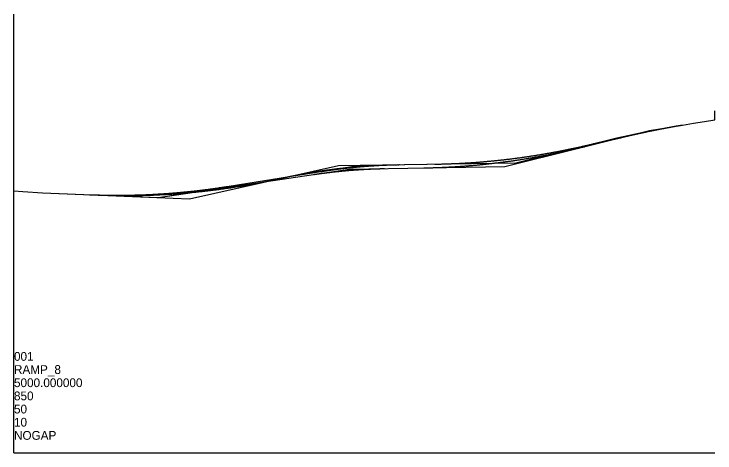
# Model space of a CAD drawing. Extents: x -26 to 16974102, y -10 to 12551234.
# Drawn here: x 179185 to 180784, y 178920 to 179920 of the extents above; entities that cross this region are included whole.
import ezdxf

# ---------------------------------------------------------------- set-up
doc = ezdxf.new("R2010")
doc.units = 0
for name, color, linetype in [('Level 28', 7, 'Continuous'), ('Level 30', 7, 'Continuous'), ('Level 31', 7, 'Continuous'), ('RD_GPK_Profile_Cell', 7, 'Continuous')]:
    doc.layers.add(name, color=color, linetype=linetype)

msp = doc.modelspace()

# ---------------------------------------------------------------- linework, layer by layer
at = {"layer": 'Level 28'}
msp.add_lwpolyline([(179185.3, 179517.1), (179205.3, 179515.6), (179250.3, 179512.6), (179515.3, 179502), (179975.3, 179575.4), (180330.3, 179580.7), (180560.3, 179637.5), (180585.3, 179643.4), (180610.3, 179648.8), (180635.3, 179653.6), (180660.3, 179658.3), (180685.3, 179662.8), (180710.3, 179667), (180735.3, 179671), (180760.3, 179674.9), (180784.4, 179678.5), (180784.4, 179682), (180784.4, 179685.3), (180784.4, 179688.6), (180784.4, 179692.1), (180784.4, 179695.5), (180784.4, 179698.8), (180784.4, 179699.2)], dxfattribs=at)
for points in [[(180145.3, 179577.9), (180149, 179578), (180152.7, 179578.1), (180156.4, 179578.2), (180160.1, 179578.2), (180163.8, 179578.3), (180167.5, 179578.4), (180171.2, 179578.5), (180174.9, 179578.7), (180178.6, 179578.8), (180182.3, 179578.9), (180186, 179579.1), (180189.7, 179579.2), (180193.4, 179579.4), (180197.1, 179579.6), (180200.8, 179579.7), (180204.5, 179579.9), (180208.2, 179580.1), (180211.9, 179580.3), (180215.6, 179580.5), (180219.3, 179580.8), (180223, 179581), (180226.7, 179581.2), (180230.4, 179581.5), (180234.1, 179581.7), (180237.8, 179582), (180241.5, 179582.3), (180245.2, 179582.6), (180248.9, 179582.9), (180252.6, 179583.2), (180256.3, 179583.5), (180260, 179583.8), (180263.7, 179584.1), (180267.4, 179584.5), (180271.1, 179584.8), (180274.8, 179585.1), (180278.5, 179585.5), (180282.2, 179585.9), (180285.9, 179586.3), (180289.6, 179586.6), (180293.3, 179587), (180297, 179587.4), (180300.7, 179587.8), (180304.4, 179588.3), (180308.1, 179588.7), (180311.8, 179589.1), (180315.5, 179589.6), (180319.2, 179590), (180322.9, 179590.5), (180326.6, 179591), (180330.3, 179591.4), (180334, 179591.9), (180337.7, 179592.4), (180341.4, 179592.9), (180345.1, 179593.5), (180348.8, 179594), (180352.5, 179594.5), (180356.2, 179595.1), (180359.9, 179595.6), (180363.6, 179596.2), (180367.3, 179596.7), (180371, 179597.3), (180374.7, 179597.9), (180378.4, 179598.5), (180382.1, 179599.1), (180385.8, 179599.7), (180389.5, 179600.3), (180393.2, 179600.9), (180396.9, 179601.6), (180400.6, 179602.2), (180404.3, 179602.9), (180408, 179603.5), (180411.7, 179604.2), (180415.4, 179604.9), (180419.1, 179605.6), (180422.8, 179606.2), (180426.5, 179607), (180430.2, 179607.7), (180433.9, 179608.4), (180437.6, 179609.1), (180441.3, 179609.9), (180445, 179610.6), (180448.7, 179611.4), (180452.4, 179612.1), (180456.1, 179612.9), (180459.8, 179613.7), (180463.5, 179614.5), (180467.2, 179615.3), (180470.9, 179616.1), (180474.6, 179616.9), (180478.3, 179617.7), (180482, 179618.5), (180485.7, 179619.4), (180489.4, 179620.2), (180493.1, 179621.1), (180496.8, 179621.9), (180500.5, 179622.8), (180504.2, 179623.7), (180507.9, 179624.6), (180511.6, 179625.5), (180515.3, 179626.4)], [(179885.3, 179561), (179887.1, 179561.3), (179888.9, 179561.6), (179890.7, 179561.9), (179892.5, 179562.2), (179894.3, 179562.4), (179896.1, 179562.7), (179897.9, 179563), (179899.7, 179563.3), (179901.5, 179563.5), (179903.3, 179563.8), (179905.1, 179564), (179906.9, 179564.3), (179908.7, 179564.6), (179910.5, 179564.8), (179912.3, 179565.1), (179914.1, 179565.3), (179915.9, 179565.5), (179917.7, 179565.8), (179919.5, 179566), (179921.3, 179566.3), (179923.1, 179566.5), (179924.9, 179566.7), (179926.7, 179567), (179928.5, 179567.2), (179930.3, 179567.4), (179932.1, 179567.6), (179933.9, 179567.8), (179935.7, 179568.1), (179937.5, 179568.3), (179939.3, 179568.5), (179941.1, 179568.7), (179942.9, 179568.9), (179944.7, 179569.1), (179946.5, 179569.3), (179948.3, 179569.5), (179950.1, 179569.7), (179951.9, 179569.9), (179953.7, 179570.1), (179955.5, 179570.3), (179957.3, 179570.4), (179959.1, 179570.6), (179960.9, 179570.8), (179962.7, 179571), (179964.5, 179571.2), (179966.3, 179571.3), (179968.1, 179571.5), (179969.9, 179571.7), (179971.7, 179571.8), (179973.5, 179572), (179975.3, 179572.1), (179977.1, 179572.3), (179978.9, 179572.5), (179980.7, 179572.6), (179982.5, 179572.8), (179984.3, 179572.9), (179986.1, 179573), (179987.9, 179573.2), (179989.7, 179573.3), (179991.5, 179573.5), (179993.3, 179573.6), (179995.1, 179573.7), (179996.9, 179573.8), (179998.7, 179574), (180000.5, 179574.1), (180002.3, 179574.2), (180004.1, 179574.3), (180005.9, 179574.4), (180007.7, 179574.5), (180009.5, 179574.7), (180011.3, 179574.8), (180013.1, 179574.9), (180014.9, 179575), (180016.7, 179575.1), (180018.5, 179575.2), (180020.3, 179575.3), (180022.1, 179575.3), (180023.9, 179575.4), (180025.7, 179575.5), (180027.5, 179575.6), (180029.3, 179575.7), (180031.1, 179575.8), (180032.9, 179575.8), (180034.7, 179575.9), (180036.5, 179576), (180038.3, 179576), (180040.1, 179576.1), (180041.9, 179576.2), (180043.7, 179576.2), (180045.5, 179576.3), (180047.3, 179576.3), (180049.1, 179576.4), (180050.9, 179576.4), (180052.7, 179576.5), (180054.5, 179576.5), (180056.3, 179576.6), (180058.1, 179576.6), (180059.9, 179576.7), (180061.7, 179576.7), (180063.5, 179576.7), (180065.3, 179576.7)], [(179357.7, 179508.3), (179360.9, 179508.2), (179364, 179508.1), (179367.2, 179508), (179370.3, 179507.9), (179373.5, 179507.8), (179376.6, 179507.7), (179379.8, 179507.6), (179382.9, 179507.5), (179386.1, 179507.4), (179389.2, 179507.4), (179392.4, 179507.3), (179395.5, 179507.3), (179398.7, 179507.2), (179401.8, 179507.2), (179405, 179507.1), (179408.2, 179507.1), (179411.3, 179507.1), (179414.5, 179507.1), (179417.6, 179507.1), (179420.8, 179507), (179423.9, 179507.1), (179427.1, 179507.1), (179430.2, 179507.1), (179433.4, 179507.1), (179436.5, 179507.1), (179439.7, 179507.2), (179442.8, 179507.2), (179446, 179507.2), (179449.1, 179507.3), (179452.3, 179507.4), (179455.4, 179507.4), (179458.6, 179507.5), (179461.8, 179507.6), (179464.9, 179507.7), (179468.1, 179507.8), (179471.2, 179507.8), (179474.4, 179508), (179477.5, 179508.1), (179480.7, 179508.2), (179483.8, 179508.3), (179487, 179508.4), (179490.1, 179508.6), (179493.3, 179508.7), (179496.4, 179508.9), (179499.6, 179509), (179502.7, 179509.2), (179505.9, 179509.3), (179509, 179509.5), (179512.2, 179509.7), (179515.3, 179509.9), (179518.5, 179510.1), (179521.7, 179510.3), (179524.8, 179510.5), (179528, 179510.7), (179531.1, 179510.9), (179534.3, 179511.1), (179537.4, 179511.3), (179540.6, 179511.6), (179543.7, 179511.8), (179546.9, 179512.1), (179550, 179512.3), (179553.2, 179512.6), (179556.3, 179512.9), (179559.5, 179513.1), (179562.6, 179513.4), (179565.8, 179513.7), (179568.9, 179514), (179572.1, 179514.3), (179575.3, 179514.6), (179578.4, 179514.9), (179581.6, 179515.2), (179584.7, 179515.5), (179587.9, 179515.9), (179591, 179516.2), (179594.2, 179516.5), (179597.3, 179516.9), (179600.5, 179517.3), (179603.6, 179517.6), (179606.8, 179518), (179609.9, 179518.4), (179613.1, 179518.7), (179616.2, 179519.1), (179619.4, 179519.5), (179622.5, 179519.9), (179625.7, 179520.3), (179628.8, 179520.7), (179632, 179521.1), (179635.2, 179521.6), (179638.3, 179522), (179641.5, 179522.4), (179644.6, 179522.9), (179647.8, 179523.3), (179650.9, 179523.8), (179654.1, 179524.3), (179657.2, 179524.7), (179660.4, 179525.2), (179663.5, 179525.7), (179666.7, 179526.2), (179669.8, 179526.7), (179673, 179527.2)]]:
    msp.add_spline(points, degree=3, dxfattribs=at)
at = {"layer": 'Level 30'}
msp.add_lwpolyline([(179185.3, 179517.1), (179205.3, 179515.6), (179250.3, 179512.6), (179515.3, 179502), (179950.3, 179566.4), (180305.3, 179572.6), (180635.3, 179654.7), (180710.3, 179667), (180735.3, 179671), (180760.3, 179674.9), (180784.4, 179678.5), (180784.4, 179682), (180784.4, 179685.3), (180784.4, 179688.6), (180784.4, 179692.1), (180784.4, 179695.5), (180784.4, 179698.8), (180784.4, 179699.2)], dxfattribs=at)
for points in [[(180560.3, 179636), (180561.8, 179636.4), (180563.3, 179636.7), (180564.8, 179637.1), (180566.3, 179637.5), (180567.8, 179637.9), (180569.3, 179638.2), (180570.8, 179638.6), (180572.3, 179638.9), (180573.8, 179639.3), (180575.3, 179639.7), (180576.8, 179640), (180578.3, 179640.4), (180579.8, 179640.7), (180581.3, 179641.1), (180582.8, 179641.5), (180584.3, 179641.8), (180585.8, 179642.2), (180587.3, 179642.5), (180588.8, 179642.9), (180590.3, 179643.2), (180591.8, 179643.6), (180593.3, 179643.9), (180594.8, 179644.2), (180596.3, 179644.6), (180597.8, 179644.9), (180599.3, 179645.3), (180600.8, 179645.6), (180602.3, 179646), (180603.8, 179646.3), (180605.3, 179646.6), (180606.8, 179647), (180608.3, 179647.3), (180609.8, 179647.6), (180611.3, 179648), (180612.8, 179648.3), (180614.3, 179648.6), (180615.8, 179648.9), (180617.3, 179649.3), (180618.8, 179649.6), (180620.3, 179649.9), (180621.8, 179650.2), (180623.3, 179650.6), (180624.8, 179650.9), (180626.3, 179651.2), (180627.8, 179651.5), (180629.3, 179651.8), (180630.8, 179652.1), (180632.3, 179652.5), (180633.8, 179652.8), (180635.3, 179653.1), (180636.8, 179653.4), (180638.3, 179653.7), (180639.8, 179654), (180641.3, 179654.3), (180642.8, 179654.6), (180644.3, 179654.9), (180645.8, 179655.2), (180647.3, 179655.5), (180648.8, 179655.8), (180650.3, 179656.1), (180651.8, 179656.4), (180653.3, 179656.7), (180654.8, 179657), (180656.3, 179657.3), (180657.8, 179657.6), (180659.3, 179657.9), (180660.8, 179658.2), (180662.3, 179658.5), (180663.8, 179658.8), (180665.3, 179659), (180666.8, 179659.3), (180668.3, 179659.6), (180669.8, 179659.9), (180671.3, 179660.2), (180672.8, 179660.5), (180674.3, 179660.7), (180675.8, 179661), (180677.3, 179661.3), (180678.8, 179661.6), (180680.3, 179661.8), (180681.8, 179662.1), (180683.3, 179662.4), (180684.8, 179662.6), (180686.3, 179662.9), (180687.8, 179663.2), (180689.3, 179663.4), (180690.8, 179663.7), (180692.3, 179664), (180693.8, 179664.2), (180695.3, 179664.5), (180696.8, 179664.8), (180698.3, 179665), (180699.8, 179665.3), (180701.3, 179665.5), (180702.8, 179665.8), (180704.3, 179666), (180705.8, 179666.3), (180707.3, 179666.5), (180708.8, 179666.8), (180710.3, 179667)], [(180120.3, 179569.3), (180124, 179569.4), (180127.7, 179569.5), (180131.4, 179569.6), (180135.1, 179569.7), (180138.8, 179569.8), (180142.5, 179569.9), (180146.2, 179570), (180149.9, 179570.1), (180153.6, 179570.3), (180157.3, 179570.4), (180161, 179570.6), (180164.7, 179570.7), (180168.4, 179570.9), (180172.1, 179571.1), (180175.8, 179571.3), (180179.5, 179571.5), (180183.2, 179571.7), (180186.9, 179571.9), (180190.6, 179572.1), (180194.3, 179572.3), (180198, 179572.6), (180201.7, 179572.8), (180205.4, 179573.1), (180209.1, 179573.4), (180212.8, 179573.6), (180216.5, 179573.9), (180220.2, 179574.2), (180223.9, 179574.5), (180227.6, 179574.8), (180231.3, 179575.1), (180235, 179575.5), (180238.7, 179575.8), (180242.4, 179576.1), (180246.1, 179576.5), (180249.8, 179576.8), (180253.5, 179577.2), (180257.2, 179577.6), (180260.9, 179578), (180264.6, 179578.4), (180268.3, 179578.8), (180272, 179579.2), (180275.7, 179579.6), (180279.4, 179580), (180283.1, 179580.5), (180286.8, 179580.9), (180290.5, 179581.4), (180294.2, 179581.8), (180297.9, 179582.3), (180301.6, 179582.8), (180305.3, 179583.3), (180309, 179583.8), (180312.7, 179584.3), (180316.4, 179584.8), (180320.1, 179585.3), (180323.8, 179585.8), (180327.5, 179586.4), (180331.2, 179586.9), (180334.9, 179587.5), (180338.6, 179588), (180342.3, 179588.6), (180346, 179589.2), (180349.7, 179589.8), (180353.4, 179590.4), (180357.1, 179591), (180360.8, 179591.6), (180364.5, 179592.2), (180368.2, 179592.9), (180371.9, 179593.5), (180375.6, 179594.2), (180379.3, 179594.8), (180383, 179595.5), (180386.7, 179596.2), (180390.4, 179596.9), (180394.1, 179597.6), (180397.8, 179598.3), (180401.5, 179599), (180405.2, 179599.7), (180408.9, 179600.4), (180412.6, 179601.1), (180416.3, 179601.9), (180420, 179602.6), (180423.7, 179603.4), (180427.4, 179604.2), (180431.1, 179605), (180434.8, 179605.7), (180438.5, 179606.5), (180442.2, 179607.3), (180445.9, 179608.2), (180449.6, 179609), (180453.3, 179609.8), (180457, 179610.7), (180460.7, 179611.5), (180464.4, 179612.4), (180468.1, 179613.2), (180471.8, 179614.1), (180475.5, 179615), (180479.2, 179615.9), (180482.9, 179616.8), (180486.6, 179617.7), (180490.3, 179618.6)], [(179870.3, 179554.5), (179871.9, 179554.8), (179873.5, 179555), (179875.1, 179555.2), (179876.7, 179555.5), (179878.3, 179555.7), (179879.9, 179555.9), (179881.5, 179556.1), (179883.1, 179556.4), (179884.7, 179556.6), (179886.3, 179556.8), (179887.9, 179557), (179889.5, 179557.2), (179891.1, 179557.4), (179892.7, 179557.6), (179894.3, 179557.8), (179895.9, 179558), (179897.5, 179558.2), (179899.1, 179558.4), (179900.7, 179558.6), (179902.3, 179558.8), (179903.9, 179559), (179905.5, 179559.2), (179907.1, 179559.4), (179908.7, 179559.6), (179910.3, 179559.8), (179911.9, 179560), (179913.5, 179560.2), (179915.1, 179560.3), (179916.7, 179560.5), (179918.3, 179560.7), (179919.9, 179560.9), (179921.5, 179561), (179923.1, 179561.2), (179924.7, 179561.4), (179926.3, 179561.5), (179927.9, 179561.7), (179929.5, 179561.9), (179931.1, 179562), (179932.7, 179562.2), (179934.3, 179562.3), (179935.9, 179562.5), (179937.5, 179562.6), (179939.1, 179562.8), (179940.7, 179562.9), (179942.3, 179563.1), (179943.9, 179563.2), (179945.5, 179563.3), (179947.1, 179563.5), (179948.7, 179563.6), (179950.3, 179563.8), (179951.9, 179563.9), (179953.5, 179564), (179955.1, 179564.1), (179956.7, 179564.3), (179958.3, 179564.4), (179959.9, 179564.5), (179961.5, 179564.6), (179963.1, 179564.7), (179964.7, 179564.9), (179966.3, 179565), (179967.9, 179565.1), (179969.5, 179565.2), (179971.1, 179565.3), (179972.7, 179565.4), (179974.3, 179565.5), (179975.9, 179565.6), (179977.5, 179565.7), (179979.1, 179565.8), (179980.7, 179565.9), (179982.3, 179566), (179983.9, 179566.1), (179985.5, 179566.2), (179987.1, 179566.2), (179988.7, 179566.3), (179990.3, 179566.4), (179991.9, 179566.5), (179993.5, 179566.6), (179995.1, 179566.6), (179996.7, 179566.7), (179998.3, 179566.8), (179999.9, 179566.9), (180001.5, 179566.9), (180003.1, 179567), (180004.7, 179567), (180006.3, 179567.1), (180007.9, 179567.2), (180009.5, 179567.2), (180011.1, 179567.3), (180012.7, 179567.3), (180014.3, 179567.4), (180015.9, 179567.4), (180017.5, 179567.5), (180019.1, 179567.5), (180020.7, 179567.6), (180022.3, 179567.6), (180023.9, 179567.6), (180025.5, 179567.7), (180027.1, 179567.7), (180028.7, 179567.7), (180030.3, 179567.8)], [(179365.3, 179508), (179368.3, 179507.9), (179371.3, 179507.8), (179374.3, 179507.7), (179377.3, 179507.6), (179380.3, 179507.5), (179383.3, 179507.4), (179386.3, 179507.3), (179389.3, 179507.2), (179392.3, 179507.2), (179395.3, 179507.1), (179398.3, 179507), (179401.3, 179507), (179404.3, 179506.9), (179407.3, 179506.9), (179410.3, 179506.8), (179413.3, 179506.8), (179416.3, 179506.8), (179419.3, 179506.8), (179422.3, 179506.7), (179425.3, 179506.7), (179428.3, 179506.7), (179431.3, 179506.7), (179434.3, 179506.7), (179437.3, 179506.7), (179440.3, 179506.8), (179443.3, 179506.8), (179446.3, 179506.8), (179449.3, 179506.9), (179452.3, 179506.9), (179455.3, 179506.9), (179458.3, 179507), (179461.3, 179507.1), (179464.3, 179507.1), (179467.3, 179507.2), (179470.3, 179507.3), (179473.3, 179507.3), (179476.3, 179507.4), (179479.3, 179507.5), (179482.3, 179507.6), (179485.3, 179507.7), (179488.3, 179507.8), (179491.3, 179507.9), (179494.3, 179508.1), (179497.3, 179508.2), (179500.3, 179508.3), (179503.3, 179508.5), (179506.3, 179508.6), (179509.3, 179508.7), (179512.3, 179508.9), (179515.3, 179509.1), (179518.3, 179509.2), (179521.3, 179509.4), (179524.3, 179509.6), (179527.3, 179509.7), (179530.3, 179509.9), (179533.3, 179510.1), (179536.3, 179510.3), (179539.3, 179510.5), (179542.3, 179510.7), (179545.3, 179511), (179548.3, 179511.2), (179551.3, 179511.4), (179554.3, 179511.6), (179557.3, 179511.9), (179560.3, 179512.1), (179563.3, 179512.4), (179566.3, 179512.6), (179569.3, 179512.9), (179572.3, 179513.1), (179575.3, 179513.4), (179578.3, 179513.7), (179581.3, 179514), (179584.3, 179514.3), (179587.3, 179514.6), (179590.3, 179514.9), (179593.3, 179515.2), (179596.3, 179515.5), (179599.3, 179515.8), (179602.3, 179516.1), (179605.3, 179516.4), (179608.3, 179516.8), (179611.3, 179517.1), (179614.3, 179517.5), (179617.3, 179517.8), (179620.3, 179518.2), (179623.3, 179518.5), (179626.3, 179518.9), (179629.3, 179519.3), (179632.3, 179519.7), (179635.3, 179520), (179638.3, 179520.4), (179641.3, 179520.8), (179644.3, 179521.2), (179647.3, 179521.6), (179650.3, 179522), (179653.3, 179522.5), (179656.3, 179522.9), (179659.3, 179523.3), (179662.3, 179523.8), (179665.3, 179524.2)]]:
    msp.add_spline(points, degree=3, dxfattribs=at)
at = {"layer": 'Level 31'}
msp.add_lwpolyline([(179185.3, 179517.1), (179205.3, 179515.6), (179250.3, 179512.6), (179585.3, 179499.2), (179925.3, 179574.6), (180330.3, 179580.7), (180560.3, 179637.5), (180585.3, 179643.4), (180610.3, 179648.8), (180635.3, 179653.6), (180660.3, 179658.3), (180685.3, 179662.8), (180710.3, 179667), (180735.3, 179671), (180760.3, 179674.9), (180784.4, 179678.5), (180784.4, 179682), (180784.4, 179685.3), (180784.4, 179688.6), (180784.4, 179692.1), (180784.4, 179695.5), (180784.4, 179698.8), (180784.4, 179699.2)], dxfattribs=at)
for points in [[(180145.3, 179577.9), (180149, 179578), (180152.7, 179578.1), (180156.4, 179578.2), (180160.1, 179578.2), (180163.8, 179578.3), (180167.5, 179578.4), (180171.2, 179578.5), (180174.9, 179578.7), (180178.6, 179578.8), (180182.3, 179578.9), (180186, 179579.1), (180189.7, 179579.2), (180193.4, 179579.4), (180197.1, 179579.6), (180200.8, 179579.7), (180204.5, 179579.9), (180208.2, 179580.1), (180211.9, 179580.3), (180215.6, 179580.5), (180219.3, 179580.8), (180223, 179581), (180226.7, 179581.2), (180230.4, 179581.5), (180234.1, 179581.7), (180237.8, 179582), (180241.5, 179582.3), (180245.2, 179582.6), (180248.9, 179582.9), (180252.6, 179583.2), (180256.3, 179583.5), (180260, 179583.8), (180263.7, 179584.1), (180267.4, 179584.5), (180271.1, 179584.8), (180274.8, 179585.1), (180278.5, 179585.5), (180282.2, 179585.9), (180285.9, 179586.3), (180289.6, 179586.6), (180293.3, 179587), (180297, 179587.4), (180300.7, 179587.8), (180304.4, 179588.3), (180308.1, 179588.7), (180311.8, 179589.1), (180315.5, 179589.6), (180319.2, 179590), (180322.9, 179590.5), (180326.6, 179591), (180330.3, 179591.4), (180334, 179591.9), (180337.7, 179592.4), (180341.4, 179592.9), (180345.1, 179593.5), (180348.8, 179594), (180352.5, 179594.5), (180356.2, 179595.1), (180359.9, 179595.6), (180363.6, 179596.2), (180367.3, 179596.7), (180371, 179597.3), (180374.7, 179597.9), (180378.4, 179598.5), (180382.1, 179599.1), (180385.8, 179599.7), (180389.5, 179600.3), (180393.2, 179600.9), (180396.9, 179601.6), (180400.6, 179602.2), (180404.3, 179602.9), (180408, 179603.5), (180411.7, 179604.2), (180415.4, 179604.9), (180419.1, 179605.6), (180422.8, 179606.2), (180426.5, 179607), (180430.2, 179607.7), (180433.9, 179608.4), (180437.6, 179609.1), (180441.3, 179609.9), (180445, 179610.6), (180448.7, 179611.4), (180452.4, 179612.1), (180456.1, 179612.9), (180459.8, 179613.7), (180463.5, 179614.5), (180467.2, 179615.3), (180470.9, 179616.1), (180474.6, 179616.9), (180478.3, 179617.7), (180482, 179618.5), (180485.7, 179619.4), (180489.4, 179620.2), (180493.1, 179621.1), (180496.8, 179621.9), (180500.5, 179622.8), (180504.2, 179623.7), (180507.9, 179624.6), (180511.6, 179625.5), (180515.3, 179626.4)], [(179795.3, 179545.8), (179797.9, 179546.4), (179800.5, 179546.9), (179803.1, 179547.5), (179805.7, 179548.1), (179808.3, 179548.6), (179810.9, 179549.2), (179813.5, 179549.7), (179816.1, 179550.2), (179818.7, 179550.8), (179821.3, 179551.3), (179823.9, 179551.8), (179826.5, 179552.3), (179829.1, 179552.8), (179831.7, 179553.4), (179834.3, 179553.8), (179836.9, 179554.3), (179839.5, 179554.8), (179842.1, 179555.3), (179844.7, 179555.8), (179847.3, 179556.3), (179849.9, 179556.7), (179852.5, 179557.2), (179855.1, 179557.6), (179857.7, 179558.1), (179860.3, 179558.5), (179862.9, 179559), (179865.5, 179559.4), (179868.1, 179559.8), (179870.7, 179560.3), (179873.3, 179560.7), (179875.9, 179561.1), (179878.5, 179561.5), (179881.1, 179561.9), (179883.7, 179562.3), (179886.3, 179562.7), (179888.9, 179563.1), (179891.5, 179563.5), (179894.1, 179563.8), (179896.7, 179564.2), (179899.3, 179564.6), (179901.9, 179564.9), (179904.5, 179565.3), (179907.1, 179565.6), (179909.7, 179566), (179912.3, 179566.3), (179914.9, 179566.6), (179917.5, 179567), (179920.1, 179567.3), (179922.7, 179567.6), (179925.3, 179567.9), (179927.9, 179568.2), (179930.5, 179568.5), (179933.1, 179568.8), (179935.7, 179569.1), (179938.3, 179569.4), (179940.9, 179569.7), (179943.5, 179569.9), (179946.1, 179570.2), (179948.7, 179570.5), (179951.3, 179570.7), (179953.9, 179571), (179956.5, 179571.2), (179959.1, 179571.5), (179961.7, 179571.7), (179964.3, 179571.9), (179966.9, 179572.2), (179969.5, 179572.4), (179972.1, 179572.6), (179974.7, 179572.8), (179977.3, 179573), (179979.9, 179573.2), (179982.5, 179573.4), (179985.1, 179573.6), (179987.7, 179573.8), (179990.3, 179573.9), (179992.9, 179574.1), (179995.5, 179574.3), (179998.1, 179574.4), (180000.7, 179574.6), (180003.3, 179574.7), (180005.9, 179574.9), (180008.5, 179575), (180011.1, 179575.2), (180013.7, 179575.3), (180016.3, 179575.4), (180018.9, 179575.5), (180021.5, 179575.6), (180024.1, 179575.7), (180026.7, 179575.8), (180029.3, 179575.9), (180031.9, 179576), (180034.5, 179576.1), (180037.1, 179576.2), (180039.7, 179576.3), (180042.3, 179576.3), (180044.9, 179576.4), (180047.5, 179576.5), (180050.1, 179576.5), (180052.7, 179576.6), (180055.3, 179576.6)], [(179375.3, 179507.6), (179379.5, 179507.4), (179383.7, 179507.3), (179387.9, 179507.2), (179392.1, 179507), (179396.3, 179506.9), (179400.5, 179506.8), (179404.7, 179506.7), (179408.9, 179506.6), (179413.1, 179506.5), (179417.3, 179506.5), (179421.5, 179506.4), (179425.7, 179506.4), (179429.9, 179506.4), (179434.1, 179506.3), (179438.3, 179506.3), (179442.5, 179506.3), (179446.7, 179506.3), (179450.9, 179506.4), (179455.1, 179506.4), (179459.3, 179506.4), (179463.5, 179506.5), (179467.7, 179506.6), (179471.9, 179506.7), (179476.1, 179506.7), (179480.3, 179506.8), (179484.5, 179507), (179488.7, 179507.1), (179492.9, 179507.2), (179497.1, 179507.4), (179501.3, 179507.5), (179505.5, 179507.7), (179509.7, 179507.9), (179513.9, 179508.1), (179518.1, 179508.3), (179522.3, 179508.5), (179526.5, 179508.7), (179530.7, 179508.9), (179534.9, 179509.2), (179539.1, 179509.4), (179543.3, 179509.7), (179547.5, 179510), (179551.7, 179510.3), (179555.9, 179510.6), (179560.1, 179510.9), (179564.3, 179511.2), (179568.5, 179511.5), (179572.7, 179511.9), (179576.9, 179512.2), (179581.1, 179512.6), (179585.3, 179513), (179589.5, 179513.3), (179593.7, 179513.7), (179597.9, 179514.1), (179602.1, 179514.6), (179606.3, 179515), (179610.5, 179515.4), (179614.7, 179515.9), (179618.9, 179516.4), (179623.1, 179516.8), (179627.3, 179517.3), (179631.5, 179517.8), (179635.7, 179518.3), (179639.9, 179518.8), (179644.1, 179519.4), (179648.3, 179519.9), (179652.5, 179520.5), (179656.7, 179521), (179660.9, 179521.6), (179665.1, 179522.2), (179669.3, 179522.8), (179673.5, 179523.4), (179677.7, 179524), (179681.9, 179524.6), (179686.1, 179525.3), (179690.3, 179525.9), (179694.5, 179526.6), (179698.7, 179527.3), (179702.9, 179528), (179707.1, 179528.7), (179711.3, 179529.4), (179715.5, 179530.1), (179719.7, 179530.8), (179723.9, 179531.5), (179728.1, 179532.3), (179732.3, 179533.1), (179736.5, 179533.8), (179740.7, 179534.6), (179744.9, 179535.4), (179749.1, 179536.2), (179753.3, 179537), (179757.5, 179537.9), (179761.7, 179538.7), (179765.9, 179539.5), (179770.1, 179540.4), (179774.3, 179541.3), (179778.5, 179542.2), (179782.7, 179543.1), (179786.9, 179544), (179791.1, 179544.9), (179795.3, 179545.8)]]:
    msp.add_spline(points, degree=3, dxfattribs=at)
at = {"layer": 'RD_GPK_Profile_Cell'}
for q in [(179185.3, 179919.9), (180784.4, 178919.9), (179185.3, 178919.9)]:
    msp.add_line((179185.3, 178919.9), q, dxfattribs=at)

# ---------------------------------------------------------------- texts
for s, p in [('001', (179185.3, 179129.9)), ('RAMP_8', (179185.3, 179099.9)), ('5000.000000', (179185.3, 179069.9)), ('850', (179185.3, 179039.9)), ('50', (179185.3, 179009.9)), ('10', (179185.3, 178979.9)), ('NOGAP', (179185.3, 178949.9))]:
    msp.add_text(s, height=20, dxfattribs=at).set_placement(p)

doc.saveas('drawing.dxf')
